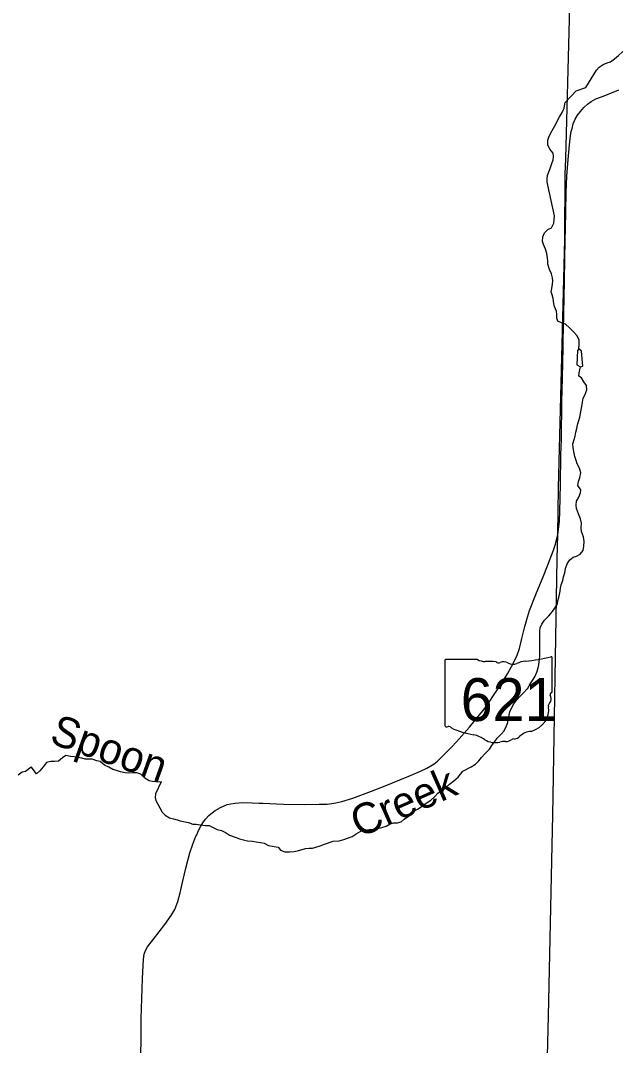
# Model space of a CAD drawing. Extents: x -6.3 to 34, y 0 to 22.
# Drawn here: x 7.479 to 8.74, y 14.392 to 16.554 of the extents above; entities that cross this region are included whole.
import ezdxf

# ---------------------------------------------------------------- set-up
doc = ezdxf.new("R2010")
doc.units = 0
for name, color, linetype in [('GM_X_Minor_Lake', 7, 'Continuous'), ('GM_X_Minor_River', 7, 'Continuous'), ('GM_X_Minor_River_Text', 7, 'Continuous'), ('GM_X_State_Location', 7, 'Continuous'), ('GM_X_State_Route', 7, 'Continuous'), ('GM_X_State_Shield', 7, 'Continuous'), ('GM_X_Township', 7, 'Continuous')]:
    doc.layers.add(name, color=color, linetype=linetype)

msp = doc.modelspace()

# ---------------------------------------------------------------- linework, layer by layer
at = {"layer": 'GM_X_Minor_Lake'}
for points in [[(8.6561, 15.8616), (8.6538, 15.8577), (8.6518, 15.8278), (8.6596, 15.8234)], [(8.6596, 15.8234), (8.6648, 15.8249), (8.6619, 15.8565), (8.6561, 15.8616)]]:
    msp.add_lwpolyline(points, dxfattribs=at)
at = {"layer": 'GM_X_Minor_River'}
for points in [[(8.6277, 16.3807), (8.651, 16.4056), (8.6712, 16.4129), (8.6936, 16.4491), (8.6993, 16.4556), (8.7078, 16.4608), (8.7161, 16.465), (8.7231, 16.4666), (8.7316, 16.4728), (8.7399, 16.4801), (8.7492, 16.4887)], [(8.6561, 15.8616), (8.6568, 15.8704), (8.6573, 15.8795), (8.6531, 15.8892), (8.6453, 15.8975), (8.6367, 15.906), (8.6284, 15.9138), (8.6211, 15.9159), (8.6123, 15.92), (8.6097, 15.9265), (8.6096, 15.9336), (8.6093, 15.9408), (8.6051, 15.9505), (8.6033, 15.957), (8.6022, 15.9676), (8.6004, 15.9752), (8.598, 15.9817), (8.5995, 15.9887), (8.601, 15.998), (8.6015, 16.0051), (8.601, 16.0116), (8.5984, 16.0199), (8.5944, 16.029), (8.591, 16.0402), (8.591, 16.0467), (8.5902, 16.0537), (8.5888, 16.0623), (8.5859, 16.0716), (8.5818, 16.0813), (8.5799, 16.088), (8.5806, 16.0974), (8.5837, 16.106), (8.5907, 16.1133), (8.5985, 16.1169), (8.6033, 16.1266), (8.6046, 16.1346), (8.6051, 16.1419), (8.5908, 16.2064), (8.5892, 16.2137), (8.5894, 16.2204), (8.5905, 16.2272), (8.593, 16.2347), (8.5956, 16.2418), (8.5994, 16.2522), (8.602, 16.2603), (8.603, 16.267), (8.6019, 16.274), (8.5954, 16.2826), (8.5907, 16.292), (8.5907, 16.3016), (8.5927, 16.3081), (8.5966, 16.3159), (8.6027, 16.3266), (8.6084, 16.3365), (8.6117, 16.3443), (8.6156, 16.3508), (8.6213, 16.3602), (8.6254, 16.369), (8.6266, 16.3781), (8.6277, 16.3807)], [(8.5478, 15.1443), (8.5514, 15.1508), (8.5555, 15.1578), (8.5602, 15.1643), (8.5641, 15.1713), (8.5674, 15.1794), (8.5705, 15.1885), (8.572, 15.1953), (8.573, 15.2018), (8.574, 15.2124), (8.5743, 15.2194), (8.574, 15.2265), (8.5742, 15.2353), (8.5739, 15.2441), (8.5742, 15.2511), (8.5744, 15.2597), (8.5741, 15.2665), (8.5746, 15.273), (8.5785, 15.281), (8.5837, 15.2891), (8.5927, 15.2985), (8.6007, 15.3073), (8.6059, 15.3146), (8.611, 15.3237), (8.612, 15.3302), (8.6144, 15.337), (8.6156, 15.3437), (8.6166, 15.3502), (8.6179, 15.3567), (8.6192, 15.364), (8.6223, 15.3729), (8.6243, 15.3807), (8.6266, 15.3895), (8.6282, 15.3986), (8.6315, 15.408), (8.6372, 15.4163), (8.6442, 15.4225), (8.6512, 15.4246), (8.6594, 15.4283), (8.6654, 15.4364), (8.6669, 15.4455), (8.6674, 15.4551), (8.6661, 15.4652), (8.6621, 15.4764), (8.6613, 15.4844), (8.6616, 15.4938), (8.6597, 15.5031), (8.6556, 15.5135), (8.6514, 15.5249), (8.6506, 15.5322), (8.6513, 15.54), (8.6562, 15.5488), (8.6596, 15.5577), (8.6603, 15.5642), (8.6543, 15.573), (8.6553, 15.5818), (8.6584, 15.5902), (8.6607, 15.6003), (8.6576, 15.6099), (8.6526, 15.619), (8.6505, 15.626), (8.6482, 15.6345), (8.6466, 15.6418), (8.6445, 15.6525), (8.644, 15.661), (8.6465, 15.6701), (8.6483, 15.6777), (8.6498, 15.6857), (8.6519, 15.6935), (8.6537, 15.7016), (8.6562, 15.7104), (8.6583, 15.7175), (8.6598, 15.7255), (8.6624, 15.7401), (8.6639, 15.7489), (8.6657, 15.7572), (8.669, 15.7637), (8.6729, 15.7749), (8.6726, 15.784), (8.6666, 15.7923), (8.6617, 15.8001), (8.6566, 15.8036), (8.6571, 15.8109), (8.6596, 15.8234)], [(7.7753, 14.9486), (7.7634, 14.9232), (7.7627, 14.9146), (7.7648, 14.9079), (7.7684, 14.9012), (7.7731, 14.8939), (7.7776, 14.8843), (7.7841, 14.8781), (7.7931, 14.8726), (7.8017, 14.8703), (7.8092, 14.868), (7.816, 14.866), (7.8227, 14.8647), (7.8331, 14.8624), (7.8422, 14.8595), (7.8492, 14.8588), (7.8575, 14.858), (7.8691, 14.8565), (7.8767, 14.856), (7.887, 14.8513), (7.8938, 14.8482), (7.9029, 14.8457), (7.9112, 14.8415), (7.92, 14.8359), (7.9337, 14.8312), (7.9408, 14.8281), (7.9491, 14.8258), (7.9579, 14.8243), (7.968, 14.8233), (7.9758, 14.8222), (7.9851, 14.8202), (7.9931, 14.8189), (8.0022, 14.814), (8.0224, 14.8109), (8.0269, 14.8042), (8.0362, 14.8011), (8.0468, 14.8011), (8.0559, 14.8014), (8.0655, 14.8033), (8.0727, 14.8059), (8.08, 14.8077), (8.0878, 14.8085), (8.0945, 14.8086), (8.1015, 14.8109), (8.1106, 14.8135), (8.1199, 14.8172), (8.1385, 14.823), (8.151, 14.8243), (8.1611, 14.8267), (8.1709, 14.8301), (8.1782, 14.833), (8.1867, 14.8387), (8.1968, 14.8444), (8.2038, 14.846), (8.2139, 14.8481), (8.2242, 14.8487), (8.232, 14.85), (8.2408, 14.8524), (8.2501, 14.8552), (8.2587, 14.8597), (8.2665, 14.8623), (8.274, 14.8623), (8.2815, 14.8644), (8.2882, 14.8694), (8.2973, 14.8762), (8.3073, 14.8858), (8.3161, 14.8908), (8.3262, 14.8973), (8.3342, 14.9033), (8.3441, 14.9098), (8.3529, 14.9176), (8.3588, 14.9244), (8.3658, 14.9294), (8.3764, 14.9372), (8.3834, 14.9434), (8.3924, 14.9502), (8.402, 14.958), (8.4117, 14.9706), (8.4296, 14.9799), (8.4384, 14.9856), (8.4453, 14.9927), (8.4509, 14.9995), (8.4581, 15.0076), (8.4676, 15.0175), (8.4728, 15.0253), (8.4795, 15.0336), (8.4842, 15.0404), (8.4924, 15.0492), (8.4992, 15.0563), (8.504, 15.0667), (8.5069, 15.0734), (8.5074, 15.0802), (8.5092, 15.0888), (8.511, 15.0963), (8.5153, 15.1049), (8.5192, 15.1132), (8.5257, 15.121), (8.5326, 15.1289), (8.5399, 15.1362), (8.5474, 15.1442)], [(7.7753, 14.9486), (7.7738, 14.9479), (7.7643, 14.9484), (7.7575, 14.9489), (7.75, 14.9506), (7.7414, 14.9563), (7.7328, 14.9644), (7.724, 14.9672), (7.7152, 14.9672), (7.7069, 14.9669), (7.6997, 14.9674), (7.6898, 14.9697), (7.6815, 14.9723), (7.6737, 14.9741), (7.6652, 14.9795), (7.6563, 14.9839), (7.6472, 14.9911), (7.6397, 14.9927), (7.6301, 14.996), (7.6234, 14.9963), (7.6151, 14.996), (7.6081, 14.998), (7.5998, 14.9996), (7.5925, 15.0011), (7.5842, 15.0021), (7.5744, 15.0037), (7.5676, 14.999), (7.5588, 14.9919), (7.5506, 14.9916), (7.5428, 14.9916), (7.5337, 14.9892), (7.5265, 14.9804), (7.5195, 14.9718), (7.5128, 14.9653), (7.5018, 14.9803)], [(7.4741, 14.9629), (7.4827, 14.9697), (7.4894, 14.9712), (7.5018, 14.9803)]]:
    msp.add_lwpolyline(points, dxfattribs=at)
at = {"layer": 'GM_X_State_Route'}
for points in [[(8.6272, 16.0915), (8.6281, 16.1142), (8.6299, 16.1909), (8.6311, 16.2258), (8.6321, 16.2433), (8.6337, 16.2605), (8.6366, 16.2916), (8.6387, 16.3105), (8.6402, 16.3199), (8.6419, 16.3265), (8.6447, 16.3358), (8.6488, 16.3458), (8.6537, 16.3541), (8.6596, 16.362), (8.667, 16.3703), (8.6748, 16.3773), (8.6826, 16.3829), (8.6924, 16.3884), (8.7095, 16.3954), (8.7405, 16.4078)], [(8.5888, 15.4001), (8.6032, 15.4367), (8.6073, 15.4497), (8.6102, 15.4614), (8.6118, 15.4697), (8.6144, 15.4859), (8.6155, 15.4978), (8.6164, 15.5188), (8.6175, 15.5762), (8.6186, 15.6375), (8.6195, 15.6714), (8.6206, 15.7504), (8.6219, 15.7997), (8.6233, 15.8643), (8.6235, 15.8806), (8.6245, 15.9302), (8.6253, 15.9758), (8.6262, 15.9992), (8.627, 16.0574), (8.6273, 16.0837), (8.6272, 16.0915)], [(7.9825, 14.9036), (7.9898, 14.9033), (8.0333, 14.9011), (8.0785, 14.9005), (8.1089, 14.9011), (8.1257, 14.9016), (8.1358, 14.9024), (8.144, 14.9038), (8.1569, 14.9067), (8.1795, 14.9142), (8.2192, 14.9289), (8.2444, 14.9389), (8.2977, 14.9601), (8.3225, 14.9707), (8.3359, 14.9771), (8.3445, 14.9819), (8.3513, 14.9866), (8.358, 14.992), (8.369, 15.0024), (8.3879, 15.0217), (8.3981, 15.033), (8.4261, 15.0636), (8.4472, 15.0895), (8.4544, 15.0989), (8.4657, 15.1143), (8.4794, 15.1347), (8.4924, 15.1544), (8.5056, 15.1765), (8.5134, 15.1901), (8.5197, 15.2022), (8.526, 15.2158), (8.5309, 15.2296), (8.5361, 15.2504), (8.5422, 15.2761), (8.5478, 15.2959), (8.5526, 15.31), (8.5658, 15.3436), (8.5825, 15.3845), (8.5888, 15.4001)], [(7.8505, 14.8369), (7.8546, 14.8455), (7.8594, 14.8549), (7.8636, 14.8621), (7.8691, 14.8696), (7.876, 14.8771), (7.8828, 14.8832), (7.8894, 14.8881), (7.9004, 14.8946), (7.9151, 14.9005), (7.9227, 14.902), (7.932, 14.9036), (7.947, 14.9045), (7.9672, 14.9043), (7.9825, 14.9036)], [(7.7326, 14.3659), (7.7334, 14.4127), (7.7337, 14.4492), (7.736, 14.5334), (7.7375, 14.5609), (7.7383, 14.5745), (7.7397, 14.585), (7.7424, 14.5927), (7.747, 14.6008), (7.7596, 14.6168), (7.7833, 14.6478), (7.7964, 14.6662), (7.8045, 14.6795), (7.8063, 14.6845), (7.8106, 14.6959), (7.8154, 14.7146), (7.8197, 14.733), (7.8279, 14.7667), (7.8364, 14.7988), (7.8422, 14.8172), (7.8489, 14.8336), (7.8505, 14.8369)]]:
    msp.add_lwpolyline(points, dxfattribs=at)
at = {"layer": 'GM_X_State_Shield'}
for p, q in [((8.3741, 15.2042), (8.3741, 15.0671)), ((8.4424, 15.2066), (8.3763, 15.2066)), ((8.5999, 15.1382), (8.5999, 15.21)), ((8.5999, 15.1383), (8.5999, 15.1382))]:
    msp.add_line(p, q, dxfattribs=at)
for centre, major_axis, start_param, end_param in [((8.3766, 15.2045), (0.00262, 0), 1.712693, 3.28349), ((8.4582, 15.2225), (0.0254, 0), 4.042523, 4.731795), ((8.4666, 15.1296), (0.0911, 0), 1.404758, 1.657858), ((8.4873, 15.2052), (0.00732, 0), 3.836095, 5.185415), ((8.498, 15.1894), (0.0152, 0), 0.950623, 2.079405), ((8.5177, 15.2111), (0.0183, 0), 4.081561, 5.145723), ((8.55, 15.1647), (0.0482, 0), 1.699011, 2.107814), ((8.5195, 15.3936), (0.2395, 0), 4.814394, 5.042369), ((8.5974, 15.2103), (0.00251, 0), 6.141152, 7.989035), ((8.5994, 15.133), (0.00389, 0), 1.883978, 3.671073), ((8.5746, 15.1239), (0.0234, 0), 5.934695, 6.695948), ((8.5973, 15.138), (0.00269, 0), 5.05454, 6.418171), ((8.6089, 15.1082), (0.017, 0), 2.387724, 3.262537), ((8.5329, 15.0991), (0.0599, 0), 5.101752, 6.440018), ((8.3767, 15.0668), (0.00264, 0), 3.00124, 4.508301), ((8.3771, 15.0808), (0.0201, 0), 4.665946, 4.897461), ((8.3812, 15.0592), (0.00726, 0), 0.519207, 1.627899), ((8.4729, 15.1824), (0.173, 0), 4.195997, 4.488961), ((8.4213, 15.0055), (0.0541, 0), 0.823519, 1.323587), ((8.5166, 15.0538), (0.0194, 0), 4.937069, 5.64225), ((8.5582, 15.0286), (0.0328, 0), 1.647645, 2.488434), ((8.4799, 15.0585), (0.0343, 0), 4.026481, 4.996735), ((8.4997, 15.0111), (0.0282, 0), 1.495662, 1.94098), ((8.5022, 15.0482), (0.0183, 0), 4.691044, 5.507374), ((8.5188, 15.0349), (0.00515, 0), 1.147584, 2.315152)]:
    msp.add_ellipse(centre, major_axis=major_axis, ratio=0.8, start_param=start_param, end_param=end_param, dxfattribs=at)
at = {"layer": 'GM_X_Township'}
msp.add_lwpolyline([(8.5851, 14.1737), (8.5926, 14.4543), (8.601, 14.8469), (8.6015, 14.8772), (8.6108, 15.419), (8.6117, 15.4701), (8.6133, 15.5687), (8.627, 16.0919), (8.6276, 16.23), (8.6289, 16.2623), (8.6446, 16.8511), (8.6445, 16.9602), (8.9341, 16.9598)], dxfattribs=at)

# ---------------------------------------------------------------- texts
at = {"layer": 'GM_X_Minor_River_Text'}
for s, rotation, p in [('Spoon', 340.331, (7.5376, 15.0312)), ('Creek', 23.7734, (8.1931, 14.8296))]:
    msp.add_text(s, height=0.0649, rotation=rotation, dxfattribs=at).set_placement(p)
at = {"layer": 'GM_X_State_Location'}
msp.add_text('621', height=0.00013, rotation=0, dxfattribs=at).set_placement((8.4386, 15.1171))
for s in ['s', 'r']:
    msp.add_text(s, height=0.00013, dxfattribs=at).set_placement((8.4845, 15.1265))
at = {"layer": 'GM_X_State_Shield'}
msp.add_text('621', height=0.09035, dxfattribs=at).set_placement((8.4073, 15.0767))

doc.saveas('drawing.dxf')
